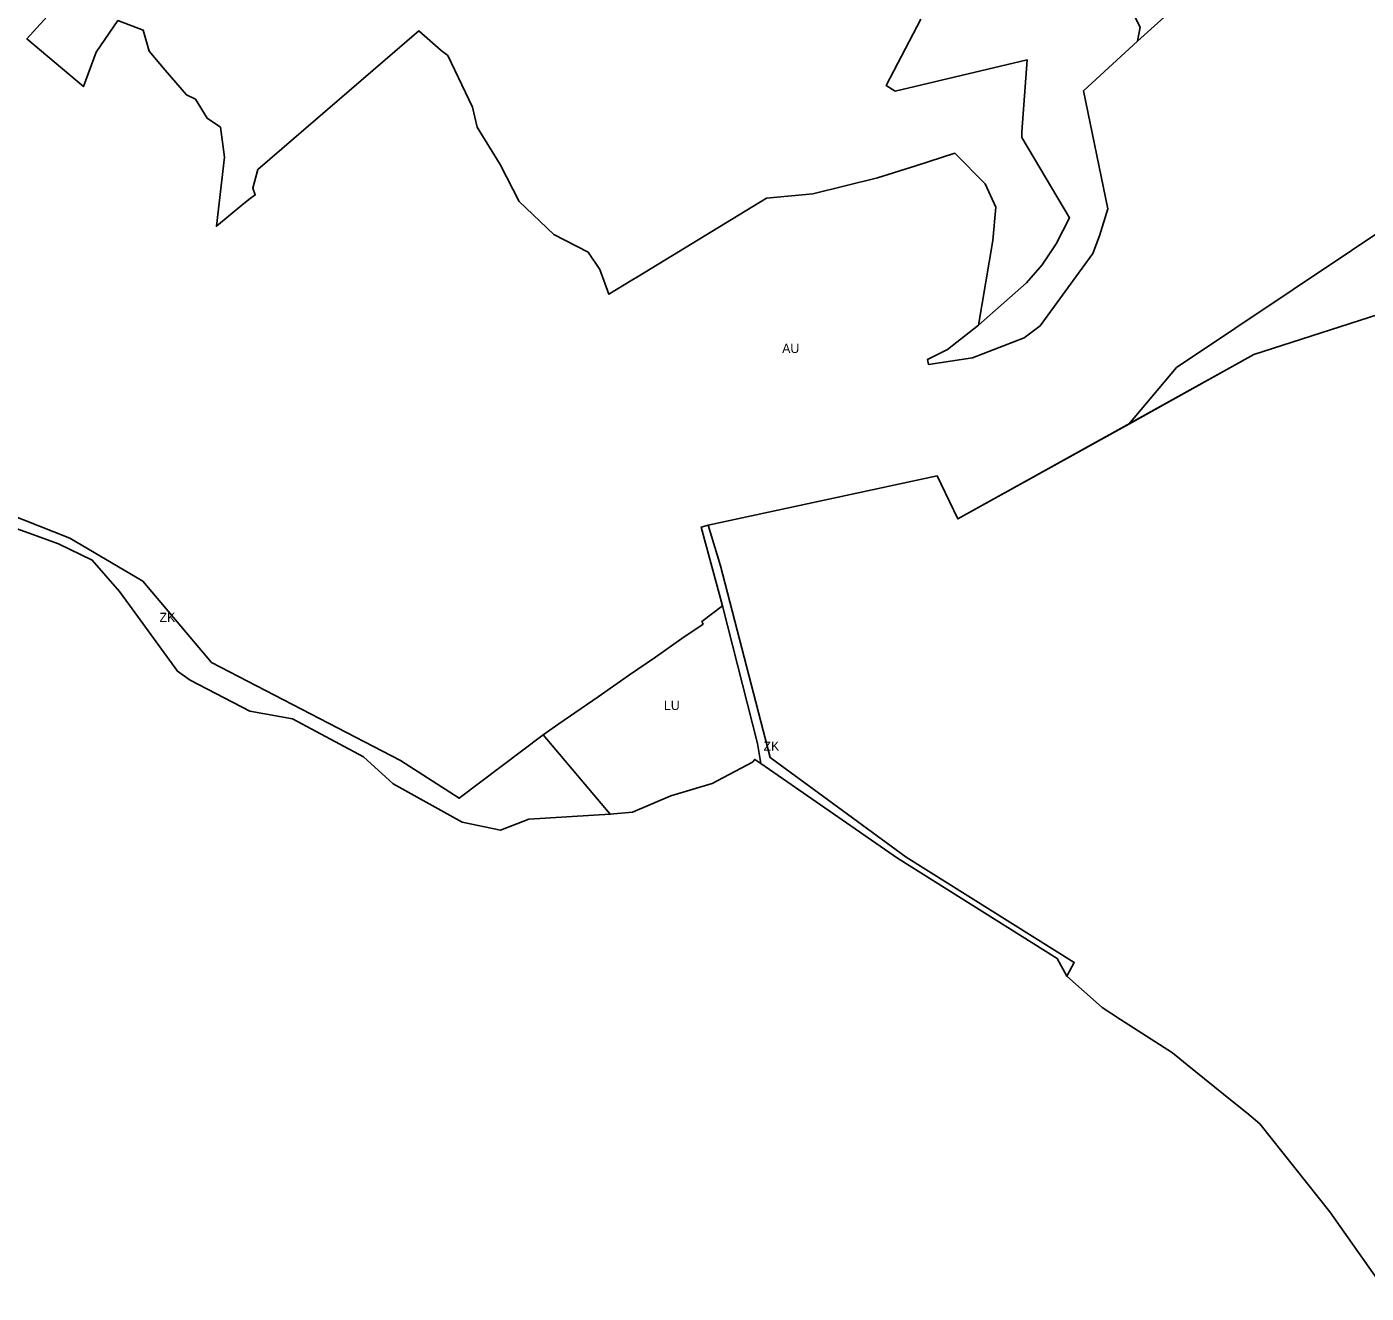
# Model space of a CAD drawing. Extents: x -521261 to -517465, y -1182764 to -1179456.
# Drawn here: x -518928 to -518203, y -1182753 to -1182068 of the extents above; entities that cross this region are included whole.
import ezdxf

# ---------------------------------------------------------------- set-up
doc = ezdxf.new("R2010")
doc.units = 0
for name, color, linetype in [('90710013', 7, 'Continuous'), ('90730013', 7, 'Continuous'), ('90750013', 7, 'Continuous'), ('90770013', 7, 'Continuous')]:
    doc.layers.add(name, color=color, linetype=linetype)

msp = doc.modelspace()

# ---------------------------------------------------------------- linework, layer by layer
at = {"layer": '90710013'}
for points in [[(-518444.19, -1182063.4), (-518462.82, -1182099.41), (-518458.01, -1182102.44), (-518386.6, -1182085.52), (-518389.43, -1182124.42), (-518389.49, -1182127.53), (-518363.62, -1182170.97), (-518370.83, -1182185.07), (-518378.46, -1182196.42), (-518386.94, -1182206.15), (-518412.83, -1182229.01), (-518405.14, -1182183.22), (-518403.47, -1182165.18), (-518409.23, -1182152.54), (-518425.645, -1182135.999), (-518446.76, -1182142.75), (-518467.48, -1182149.36), (-518502.65, -1182158.02), (-518527.66, -1182160.32), (-518597.56, -1182202.93), (-518600.56, -1182204.73), (-518612.93, -1182212.35), (-518617.97, -1182198.92), (-518624.12, -1182189.53), (-518642.72, -1182180.05), (-518661.49, -1182162.15), (-518671.83, -1182142.12), (-518684.29, -1182121.97), (-518686.86, -1182111.13), (-518700.25, -1182083.11), (-518703.84, -1182080.32), (-518715.88, -1182069.82), (-518802.99, -1182144.82), (-518805.75, -1182154.86), (-518804.47, -1182158.53), (-518807.22, -1182160.43), (-518810.55, -1182163.14), (-518825.45, -1182175.55), (-518821.12, -1182138.11), (-518823.16, -1182121.89), (-518830.45, -1182117.06), (-518836.85, -1182106.7), (-518841.68, -1182104.3), (-518853.17, -1182091.09), (-518861.95, -1182080.69), (-518865.04, -1182069.45), (-518878.76, -1182064.07), (-518890.47, -1182081.22), (-518897.42, -1182099.88), (-518928.06, -1182074.15), (-518913.53, -1182057.93)], [(-518988.83, -1182311.11), (-518904.79, -1182344.46), (-518865.37, -1182367.72), (-518828.06, -1182411.68), (-518725.77, -1182464.65), (-518693.954, -1182485.155), (-518648.65, -1182450.88), (-518612.29, -1182493.83), (-518656.41, -1182496.56), (-518671.74, -1182502.4), (-518692.39, -1182498.07), (-518729.72, -1182477.4), (-518745.79, -1182462.67), (-518784.2, -1182442.1), (-518807.32, -1182438.02), (-518839.75, -1182421.31), (-518846.6, -1182416.39), (-518872.51, -1182380.67), (-518877.96, -1182373.17), (-518892.64, -1182356.33), (-518910.86, -1182347.51), (-519003.18, -1182314)]]:
    msp.add_lwpolyline(points, dxfattribs=at)
for points in [[(-518263.83, -1182245.02), (-518331.496, -1182282.593), (-518305.68, -1182252.07), (-518179.3, -1182167.62), (-518137.82, -1182142.72), (-517980.99, -1182067.93), (-518025.29, -1182113.9), (-518027.56, -1182111.28), (-518111.08, -1182158.35), (-518153.43, -1182170.1), (-518139.38, -1182204.87)], [(-518525.73, -1182463.17), (-518451.99, -1182517.08), (-518361.09, -1182574.04), (-518365, -1182581.49), (-518370.23, -1182571.92), (-518456.78, -1182517.53), (-518530.75, -1182466.4), (-518532.52, -1182455.61), (-518551.47, -1182380.97), (-518563.11, -1182338.38), (-518559.26, -1182337.41), (-518552.56, -1182359.4)]]:
    msp.add_lwpolyline(points, close=True, dxfattribs=at)
at = {"layer": '90730013'}
msp.add_lwpolyline([(-518296.03, -1182047.39), (-518326.89, -1182075.42), (-518325.37, -1182067.68), (-518332.06, -1182054.74)], dxfattribs=at)
at = {"layer": '90750013'}
for points in [[(-518913.53, -1182057.93), (-518928.06, -1182074.15), (-518897.42, -1182099.88), (-518890.47, -1182081.22), (-518878.76, -1182064.07), (-518865.04, -1182069.45), (-518861.95, -1182080.69), (-518853.17, -1182091.09), (-518841.68, -1182104.3), (-518836.85, -1182106.7), (-518830.45, -1182117.06), (-518823.16, -1182121.89), (-518821.12, -1182138.11), (-518825.45, -1182175.55), (-518810.55, -1182163.14), (-518807.22, -1182160.43), (-518804.47, -1182158.53), (-518805.75, -1182154.86), (-518802.99, -1182144.82), (-518715.88, -1182069.82), (-518703.84, -1182080.32), (-518700.25, -1182083.11), (-518686.86, -1182111.13), (-518684.29, -1182121.97), (-518671.83, -1182142.12), (-518661.49, -1182162.15), (-518642.72, -1182180.05), (-518624.12, -1182189.53), (-518617.97, -1182198.92), (-518612.93, -1182212.35), (-518600.56, -1182204.73), (-518597.56, -1182202.93), (-518527.66, -1182160.32), (-518502.65, -1182158.02), (-518467.48, -1182149.36), (-518446.76, -1182142.75), (-518425.645, -1182135.999), (-518409.23, -1182152.54), (-518403.47, -1182165.18), (-518405.14, -1182183.22), (-518412.83, -1182229.01), (-518429.66, -1182242.3), (-518440.48, -1182247.57), (-518439.99, -1182250.28), (-518416.09, -1182246.77), (-518388.22, -1182235.99), (-518379.47, -1182229.52), (-518350.96, -1182190.35), (-518347.31, -1182180.7), (-518342.86, -1182166.04), (-518356.01, -1182102.22), (-518326.89, -1182075.42), (-518296.03, -1182047.39)], [(-518179.3, -1182167.62), (-518305.68, -1182252.07), (-518331.496, -1182282.593), (-518424.06, -1182333.99), (-518433.13, -1182315.06), (-518435.2, -1182310.64), (-518559.26, -1182337.41), (-518563.11, -1182338.38), (-518551.47, -1182380.97), (-518562.67, -1182389.49), (-518562.01, -1182390.85), (-518573.44, -1182398.77), (-518587.82, -1182408.73), (-518601.78, -1182418.4), (-518618.86, -1182430.24), (-518640.01, -1182444.89), (-518648.65, -1182450.88), (-518693.954, -1182485.155), (-518725.77, -1182464.65), (-518828.06, -1182411.68), (-518865.37, -1182367.72), (-518904.79, -1182344.46), (-518988.83, -1182311.11)]]:
    msp.add_lwpolyline(points, dxfattribs=at)
at = {"layer": '90770013'}
for points in [[(-518332.06, -1182054.74), (-518325.37, -1182067.68), (-518326.89, -1182075.42), (-518356.01, -1182102.22), (-518342.86, -1182166.04), (-518347.31, -1182180.7), (-518350.96, -1182190.35), (-518379.47, -1182229.52), (-518388.22, -1182235.99), (-518416.09, -1182246.77), (-518439.99, -1182250.28), (-518440.48, -1182247.57), (-518429.66, -1182242.3), (-518412.83, -1182229.01), (-518386.94, -1182206.15), (-518378.46, -1182196.42), (-518370.83, -1182185.07), (-518363.62, -1182170.97), (-518389.49, -1182127.53), (-518389.43, -1182124.42), (-518386.6, -1182085.52), (-518458.01, -1182102.44), (-518462.82, -1182099.41), (-518444.19, -1182063.4)], [(-518191.58, -1182753.11), (-518222.72, -1182708.99), (-518260.64, -1182661.33), (-518267.61, -1182655.55), (-518275.54, -1182649.17), (-518299.9, -1182629.46), (-518307.86, -1182623), (-518335.95, -1182604.96), (-518346.01, -1182598.51), (-518365, -1182581.49), (-518361.09, -1182574.04), (-518451.99, -1182517.08), (-518525.73, -1182463.17), (-518552.56, -1182359.4), (-518559.26, -1182337.41), (-518435.2, -1182310.64), (-518433.13, -1182315.06), (-518424.06, -1182333.99), (-518263.83, -1182245.02), (-518139.38, -1182204.87)]]:
    msp.add_lwpolyline(points, dxfattribs=at)
msp.add_lwpolyline([(-518562.01, -1182390.85), (-518562.67, -1182389.49), (-518551.47, -1182380.97), (-518532.52, -1182455.61), (-518530.75, -1182466.4), (-518534.03, -1182464.13), (-518535.31, -1182465.71), (-518557.06, -1182477.23), (-518579.44, -1182483.85), (-518600.27, -1182492.68), (-518612.29, -1182493.83), (-518648.65, -1182450.88), (-518640.01, -1182444.89), (-518618.86, -1182430.24), (-518601.78, -1182418.4), (-518587.82, -1182408.73), (-518573.44, -1182398.77)], close=True, dxfattribs=at)

# ---------------------------------------------------------------- texts
at = {"layer": '90710013'}
for p in [(-518856.265, -1182389.791), (-518529.291, -1182459.45)]:
    msp.add_text('ZK', height=5, rotation=360, dxfattribs=at).set_placement(p)
at = {"layer": '90750013'}
msp.add_text('AU', height=5, rotation=0, dxfattribs=at).set_placement((-518519.182, -1182244.151))
at = {"layer": '90770013'}
msp.add_text('LU', height=5, rotation=360, dxfattribs=at).set_placement((-518583.17, -1182437.4))

doc.saveas('drawing.dxf')
